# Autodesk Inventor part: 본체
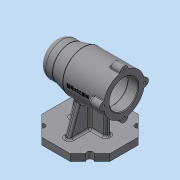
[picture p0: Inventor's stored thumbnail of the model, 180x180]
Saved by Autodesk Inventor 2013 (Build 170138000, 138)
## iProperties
Created: 2021-01
Part Number: 본체
Material: Generic
Document SubType Name: Modeling
Designer: Administrator
Density: 1 g/cm^3
Author: Administrator
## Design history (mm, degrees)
sketch "스케치1"
  geometry: L1 (50, -20.711)-(20.711, -50); L2 (20.711, -50)-(-20.711, -50); L3 (-20.711, -50)-(-50, -20.711); L4 (-50, -20.711)-(-50, 20.711); L5 (-50, 20.711)-(-20.711, 50); L6 (-20.711, 50)-(20.711, 50); L7 (20.711, 50)-(50, 20.711); L8 (50, 20.711)-(50, -20.711); 3 further points
  constraints: 16 end point, 1 coincident, 1 horizontal alignment, 1 midpoint, 17 other
  dimensions: "d0" = 50 distance from line of L8 point (0, 0)
extrude "돌출1" new body sketch "스케치1" distance "d1" = 10; taper "d2" = 0 deg
sketch "스케치2"
  geometry: L1 (20.711, 0)-(-20.711, 0) reference; L2 (50, 75)-(-50, 75); L3 (-20.711, 0)-(-50, 0) reference; L4 (50, 0)-(20.711, 0) reference; L5 (50, 75)-(50, 100); L6 (50, 100)-(30, 100); L7 (30, 100)-(10, 105); L8 (10, 105)-(-50, 105); L9 (-50, 105)-(-50, 75); L10 (37, 75)-(37, 92.5); L11 (37, 92.5)-(19, 92.5); L12 (19, 92.5)-(19, 96); L13 (19, 96)-(7, 96); L14 (7, 96)-(7, 99); L15 (7, 99)-(-35, 99); L16 (-35, 99)-(-35, 96); L17 (-35, 96)-(-50, 96); 1 further point
  constraints: 28 end point, 8 parallel, 5 perpendicular, 2 point on line, 1 vertical alignment
  dimensions: "d3" = 100 distance of L2.start L2.end; "d5" = 75 distance from line of L4.start L2; "d6" = 20 distance of L5.end L6.end; "d7" = 60 distance of L7.end L8.end; "d8" = 50 diameter of L6 L2; "d9" = 60 diameter of L8 L2; "d10" = 15 distance of L16.end L17.end; "d11" = 42 distance of L14.end L15.end; "d12" = 12 distance of L12.end L13.end; "d13" = 18 distance of L10.end L11.end; "d14" = 35 diameter of L11 L2; "d15" = 42 diameter of L13 L2; "d16" = 48 diameter of L15 L2; "d17" = 42 diameter of L17 L2
revolve "회전1" sketch "스케치2" stored, may be unused: angle "d18" = 90 deg
sketch "스케치3"
  geometry: L1 (-20.711, 10)-(-50, 10) reference; L2 (50, 10)-(20.711, 10) reference; L3 (20.711, 10)-(-20.711, 10) reference; L4 (35, 10)-(19.606, 52.293); L5 (-19.606, 52.293)-(-35, 10); A1 r 30 centre (0, 75) between (19.606, 52.293) and (-19.606, 52.293) reference; 1 further point
  constraints: 4 end point, 2 point on circle, 2 point on line
  dimensions: "d19" = 15 distance of L2.start L4.start; "d20" = 15 distance of L5.end L1.end; "d21" = 110 deg angle of L1 L5; "d22" = 110 deg angle of L2 L4
extrude "돌출2" join sketch "스케치3" stored distance "d23" = 8; taper "d24" = 0 deg
sketch "스케치4"
  geometry: L1 (0, 4)-(27, 4); L2 (27, 4)-(27, -4); L3 (27, -4)-(0, -4); L4 (0, -4)-(0, 4); L5 (50, 20.711)-(50, -20.711) reference; 2 further points
  constraints: 8 end point, 2 parallel, 1 coincident, 1 horizontal, 1 midpoint, 1 perpendicular
  dimensions: "d25" = 8 distance of L1.end L2.end; "d27" = 23 distance between parallel lines of L5 L2
extrude "돌출3" join sketch "스케치4" stored distance "d28" = 8; taper "d29" = 0 deg
sketch "스케치5"
  geometry: L1 (10, 45)-(30, 50) reference; L2 (-50, 45)-(10, 45) reference; L3 (4, 10)-(4, 52.293) reference; L4 (20.711, 10)-(-20.711, 10) reference; L5 (50, 10)-(20.711, 10) reference; L6 (19.724, 47.431)-(27, 10); 1 further point
  constraints: 2 end point, 2 point on line
  dimensions: "d30" = 23 distance of L5.start L6.end; "d31" = 101 deg angle of L5 L6
feature "리브1" sketch "스케치5" dims "d32" = 1, "d33" = 8, "d34" = 0, "d35" = 0, "d36" = 1, "d37" = 1
sketch "스케치6"
  geometry: L1 (50, 20.711)-(50, -20.711) reference; L2 (50, -20.711)-(20.711, -50) reference; L3 (20.711, -50)-(-20.711, -50) reference; L4 (-20.711, -50)-(-50, -20.711) reference; L5 (-50, -20.711)-(-50, 20.711) reference; L6 (-50, 20.711)-(-20.711, 50) reference; L7 (-20.711, 50)-(20.711, 50) reference; L8 (20.711, 50)-(50, 20.711) reference; 5 further points
  constraints: 4 midpoint
hole "구멍1" sketch "스케치6" at (35.355, 35.355), (-35.355, 35.355), (-35.355, -35.355), (35.355, -35.355) diameter "d38" = 9; stored, may be unused: countersink angle "d42" = 90 deg, drill point angle "d44" = 118 deg; dims "d39" = 6, "d40" = 4, "d41" = 2, "d43" = 8
sketch "스케치7"
  geometry: C1 r 6 at (0, -30); C2 r 6 at (30, 0); C3 r 6 at (0, 30); C4 r 6 at (-30, 0); 2 further points
  constraints: 4 centre point, 2 vertical alignment, 10 other
  dimensions: "d47" = 360 deg dimension on point (0, 0) C1.centre (derived); "d49" = 12 diameter of C1
extrude "돌출4" join sketch "스케치7" distance "d50" = 16; taper "d51" = 0 deg
sketch "스케치8"
  geometry: C1 r 21 at (-30, 0) reference; A1 r 30 centre (-30, 0) between (-59.4, -5.97) and (-35.97, -29.4) reference; A2 r 6 centre (-30, -30) between (-35.97, -29.4) and (-24.03, -29.4) reference; A3 r 30 centre (-30, 0) between (-24.03, -29.4) and (-0.6, -5.97) reference; A4 r 6 centre (0, 0) between (-0.6, -5.97) and (-0.6, 5.97) reference; A5 r 30 centre (-30, 0) between (-0.6, 5.97) and (-24.03, 29.4) reference; A6 r 6 centre (-30, 30) between (-24.03, 29.4) and (-35.97, 29.4) reference; A7 r 30 centre (-30, 0) between (-35.97, 29.4) and (-59.4, 5.97) reference; A8 r 6 centre (-60, 0) between (-59.4, 5.97) and (-59.4, -5.97) reference; 1 further point
hole "구멍2" sketch "스케치8" at (-60, 0) diameter "d52" = 3.242; stored, may be unused: countersink angle "d56" = 90 deg, drill point angle "d58" = 118 deg; dims "d53" = 8, "d54" = 4, "d55" = 2, "d57" = 10
node "작업 평면1"
sketch "스케치9"
  geometry: L1 (-30, 100)-(-30, 50) reference; L2 (50, 104.4)-(50, 80.97) reference; 3 further points
  constraints: 1 horizontal alignment, 1 midpoint, 1 other
  dimensions: "d63" = 38 distance from line of L2 point (12, 75)
feature "엠보싱1" sketch "스케치9" dims "d0" = 50, "d3" = 100, "d5" = 75, "d6" = 20, "d7" = 60, "d8" = 50, "d9" = 60, "d10" = 15, "d11" = 42, "d12" = 12, "d13" = 18, "d14" = 35, "d15" = 42, "d16" = 48, "d17" = 42, "d64" = 0.5, "d65" = 0
chamfer "모따기1" distance "d66" = 1; stored, may be unused: second distance "d67" = 2, angle "d68" = 45 deg
fillet "모깎기1" dims "d69" = 3
sketch "스케치10"
  geometry: C1 r 17.5 at (0, 0) reference; C2 r 16 at (0, 0); 1 further point
  constraints: 1 centre point, 1 coincident
  dimensions: "d70" = 32 diameter of C2
extrude "돌출5" cut sketch "스케치10" distance "d72" = 4; taper "d73" = 0 deg
sketch "스케치11"
  geometry: C1 r 16 at (0, 0) reference; C2 r 10.5 at (0, 0); 1 further point
  constraints: 1 centre point, 1 coincident
  dimensions: "d74" = 21 diameter of C2
extrude "돌출6" cut sketch "스케치11" distance "d76" = 3; taper "d77" = 0 deg
fillet "모깎기2" dims "d78" = 10
fillet "모깎기3" dims "d79" = 3
fillet "모깎기4" dims "d80" = 0.3
fillet "모깎기5" dims "d81" = 3
fillet "모깎기6" dims "d82" = 1
fillet "모깎기7" dims "d83" = 3
fillet "모깎기8" dims "d84" = 3
fillet "모깎기9" dims "d85" = 3
node "솔리드1"
pattern_circular "원형 패턴1" dims angle "d60" = 360 deg
node "투영된 루프1"
node "투영된 루프2"
node "투영된 루프3"
node "투영된 루프4"
